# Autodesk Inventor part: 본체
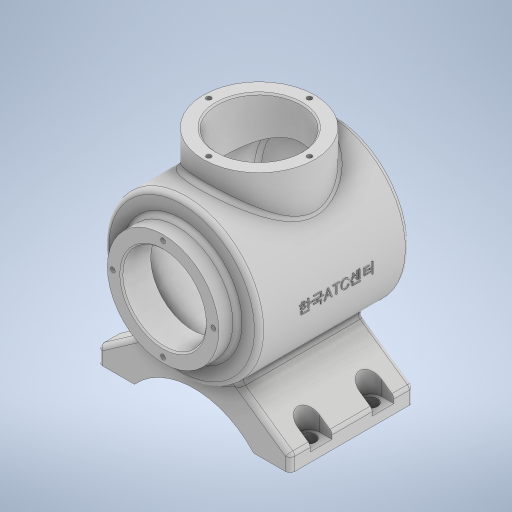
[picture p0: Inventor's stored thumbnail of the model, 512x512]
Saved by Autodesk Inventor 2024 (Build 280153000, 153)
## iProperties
Created: 2023-08
Part Number: 본체
Material: 일반
Document SubType Name: Modeling
Designer: Owner
Density: 1 g/cm^3
Appearance: 기본값
Mass: 480.256 g
Surface Area: 1060.44 cm^2
Volume: 480.256 cm^3
Author: Owner
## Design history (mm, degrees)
sketch "스케치1"
  geometry: L1 (0, 0)-(0, -120); L2 (36, 0)-(36, -12); L3 (36, -12)-(50, -12); L4 (50, -12)-(50, -108.336); L5 (27, -19)-(43, -19); L6 (43, -19)-(43, -103.887); L7 (27, -19)-(27, 0); L8 (27, 0)-(36, 0); A1 r 113 centre (0, -7) between (0, -120) and (50, -108.336); A2 r 106 centre (0, -7) between (0, -113) and (43, -103.887)
  constraints: 16 end point, 4 point on circle, 4 vertical, 2 centre point, 2 perpendicular, 2 point on line, 1 horizontal alignment, 2 other
  dimensions: "d0" = 120 distance of L1.start L1.end; "d1" = 113 radius of A1; "d2" = 72 diameter of L2 L1; "d3" = 100 diameter of L4 L1; "d4" = 108 distance from line of L1.end L3; "d5" = 7 radial gap between concentric circles of A1 A2; "d6" = 54 diameter of L7 L1
revolve "회전1" sketch "스케치1" stored, may be unused: angle "d7" = 90 deg
fillet "모깎기1" dims "d8" = 3
node "작업 평면1"
sketch "스케치2"
  geometry: C1 r 36 at (0, -62); 1 further point
  constraints: 1 centre point, 1 vertical alignment
  dimensions: "d10" = 72 diameter of C1; "d11" = 62 distance of point (0, 0) C1.centre
extrude "돌출1" join sketch "스케치2" stored distance "d12" = 10; taper "d13" = 0 deg
sketch "스케치3"
  geometry: C1 r 36 at (0, 0) reference; 2 further points
  constraints: 1 coincident
hole "구멍1" sketch "스케치3" at (0, 0) diameter "d14" = 54; stored, may be unused: countersink angle "d18" = 90 deg, drill point angle "d20" = 118 deg; dims "d15" = 8, "d16" = 4, "d17" = 2, "d19" = 48
sketch "스케치4"
  geometry: C1 r 27 at (0, 0) reference; 2 further points
  constraints: 1 vertical alignment
  dimensions: "d21" = 32.5 distance of C1.centre point (0, 32.5)
hole "구멍2" sketch "스케치4" at (0, 32.5) diameter "d22" = 3.242; stored, may be unused: countersink angle "d26" = 90 deg, drill point angle "d28" = 118 deg; dims "d23" = 8, "d24" = 4, "d25" = 2, "d27" = 10
sketch "스케치5"
  geometry: 2 further points
  constraints: 1 vertical alignment
  dimensions: "d32" = 32.5 distance of point (0, 0) point (0, 32.5)
hole "구멍3" sketch "스케치5" at (0, 32.5) diameter "d33" = 3.242; stored, may be unused: countersink angle "d37" = 90 deg, drill point angle "d39" = 118 deg; dims "d34" = 8, "d35" = 4, "d36" = 2, "d38" = 10
fillet "모깎기2" dims "d43" = 3
node "작업 평면2"
sketch "스케치6"
  geometry: L1 (-62, -67)-(-62, -77); L2 (-62, -77)-(-38.5, -77); L3 (26.694, -42.278)-(62, -67); L4 (62, -67)-(62, -77); L5 (62, -77)-(38.5, -77); L6 (-62, -67)-(-26.694, -42.278); A1 r 50 centre (0, 0) between (26.694, -42.278) and (-26.694, -42.278) reference; A2 r 52.096 centre (0, -112.096) between (38.5, -77) and (-38.5, -77); 2 further points
  constraints: 12 end point, 5 point on circle, 3 equal length, 2 perpendicular, 2 vertical, 2 vertical alignment, 1 centre point
  dimensions: "d45" = 17 distance from line of L5 point (0, -60); "d47" = 55 deg angle of L4 L3; "d48" = 10 distance of L4.end L3.end; "d49" = 77 distance of L2.end L5.end; "d50" = 124 distance of L4.end L1.end; "d51" = 77 distance from line of L5 point (0, 0)
extrude "돌출2" join sketch "스케치6" stored distance "d52" = 80; taper "d53" = 0 deg
node "작업 평면3"
sketch "스케치7"
  geometry: L1 (-54, -80)-(-79.632, -80); L2 (-54, -73)-(-62, -73); L3 (-62, -87)-(-54, -87); L4 (-62, -100)-(-38.5, -100) reference; L5 (-62, -100)-(-62, -20) reference; L6 (54, -80)-(75.93, -80); L7 (54, -73)-(62, -73); L8 (62, -87)-(54, -87); L9 (62, -20)-(62, -100) reference; A1 r 7 centre (-54, -80) between (-54, -87) and (-54, -73); A2 r 7 centre (54, -80) between (54, -73) and (54, -87); 3 further points
  constraints: 16 end point, 4 horizontal, 4 point on circle, 4 point on line, 4 tangent, 2 centre point, 2 midpoint, 2 parallel, 1 horizontal alignment
  dimensions: "d55" = 20 distance between parallel lines of L4 L1; "d56" = 14 distance between parallel lines of L3 L2; "d57" = 8 distance from line of L5 L1.start; "d58" = 14 distance between parallel lines of L8 L7; "d59" = 8 distance from line of L9 L6.start
extrude "돌출3" cut sketch "스케치7" distance "d60" = 21.5; taper "d61" = 0 deg
sketch "스케치8"
  geometry: A1 r 7 centre (54, 80) between (54, 87) and (54, 73) reference; 2 further points
  constraints: 1 coincident
hole "구멍4" sketch "스케치8" at (54, 80) diameter "d62" = 9; stored, may be unused: countersink angle "d66" = 90 deg, drill point angle "d68" = 118 deg; dims "d63" = 8, "d64" = 4, "d65" = 2, "d67" = 10
fillet "모깎기3" dims "d72" = 3
fillet "모깎기4" dims "d73" = 3
fillet "모깎기5" dims "d74" = 3
chamfer "모따기1" distance "d75" = 1; stored, may be unused: second distance "d76" = 2, angle "d77" = 45 deg
node "작업 평면4"
sketch "스케치9"
  geometry: L1 (-36, 60.168)-(36, 60.168) reference; 3 further points
  constraints: 1 midpoint, 1 vertical alignment, 1 other
  dimensions: "d78" = 62 distance from line of L1 point (0, -1.832)
feature "엠보싱1" sketch "스케치9" dims "d0" = 120, "d1" = 113, "d2" = 72, "d3" = 100, "d4" = 108, "d5" = 7, "d6" = 54, "d79" = 0.5, "d80" = 0
node "솔리드1"
pattern_circular "원형 패턴1" dims angle "d30" = 360 deg
pattern_circular "원형 패턴2" dims angle "d41" = 360 deg
mirror "미러1"
pattern_linear "직사각형 패턴1" dims "d71" = 40
feature "A9D066F2-1C7D-4E18-AEED-F7BC21143FA4" dims "d14" = 54, "d15" = 8, "d16" = 4, "d17" = 2, "d18" = 90 deg, "d19" = 48, "d20" = 118 deg
other parameters: "d9" = 65, "d54" = -71
